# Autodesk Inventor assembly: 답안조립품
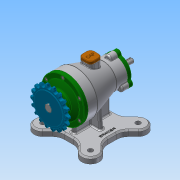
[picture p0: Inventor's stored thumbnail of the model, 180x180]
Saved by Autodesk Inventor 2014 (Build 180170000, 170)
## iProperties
Created: 2018-03
Part Number: 답안조립품
Document SubType Name: Assembly
Designer: 703
Author: 703
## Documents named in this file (15)
- C:\Users\user\Desktop\480307V1003\답안조립품.iam
- C:\Users\user\Desktop\480307V1003\본체.ipt
- C:\Users\user\Desktop\480307V1003\뒤커버.ipt
- C:\Users\user\Desktop\480307V1003\앞커버.ipt
- C:\Users\user\Desktop\480307V1003\마개.ipt
- C:\Users\user\Desktop\480307V1003\베어링-6203.ipt
- C:\Users\user\Desktop\480307V1003\베어링-6200.ipt
- C:\Users\user\Desktop\480307V1003\축.ipt
- C:\Users\user\Desktop\480307V1003\오일 실 17 30 8.ipt
- C:\Users\user\Desktop\480307V1003\오일 실 10 20 7.ipt
- C:\Users\user\Desktop\480307V1003\키 5 x 5.ipt
- 키 5 x 5.ipt
- C:\Users\user\Desktop\480307V1003\스프로킷.ipt
- C:\Users\user\Desktop\480307V1003\볼트 M4 x 12.ipt
- 볼트 M4 x 12.ipt
